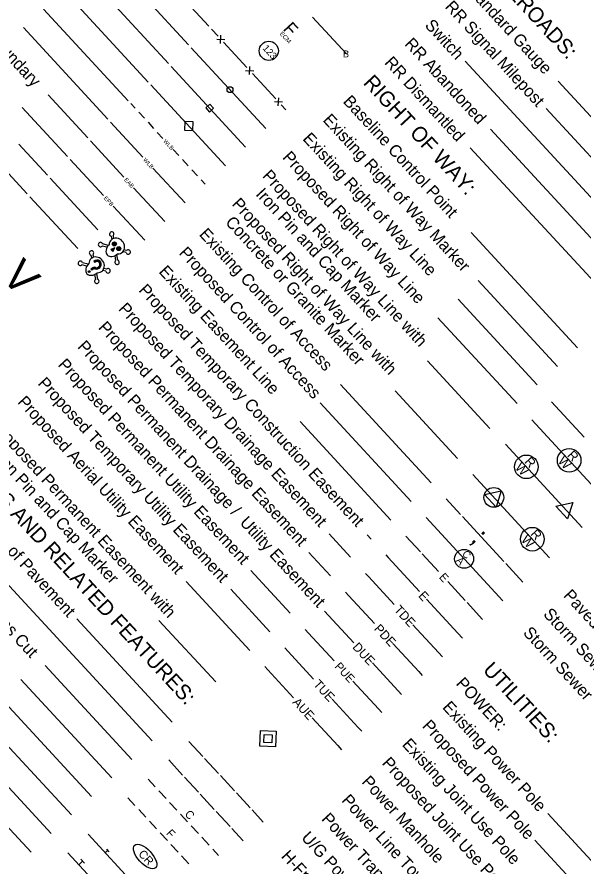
# Model space of a CAD drawing. Extents: x 1695041 to 1706254, y 786537 to 798223.
# Drawn here: x 1700036 to 1700861, y 791621 to 792859 of the extents above; entities that cross this region are included whole.
import ezdxf

# ---------------------------------------------------------------- set-up
doc = ezdxf.new("R2010")
doc.units = 0
for name, color, linetype in [('Prop Easement Permanent Drainage Utility', 7, 'Continuous'), ('Prop ROW Permanent Easement CELL', 7, 'Continuous'), ('Prop WCC CELL', 7, 'Continuous'), ('Sheet Symbology CELL', 7, 'Continuous')]:
    doc.layers.add(name, color=color, linetype=linetype)

msp = doc.modelspace()

# ---------------------------------------------------------------- linework, layer by layer
at = {"layer": 'Prop Easement Permanent Drainage Utility'}
for p, q in [((1700484.5, 791993.8), (1700527, 791947.8)), ((1700554.1, 791918.5), (1700596.4, 791872.6))]:
    msp.add_line(p, q, dxfattribs=at)
at = {"layer": 'Prop ROW Permanent Easement CELL'}
msp.add_line((1700401.9, 791808.3), (1700401.9, 791808.3), dxfattribs=at)
for points in [[(1700413.8, 791819.3), (1700412.8, 791796.5), (1700390.1, 791797.4), (1700391, 791820.2)], [(1700407.8, 791813.8), (1700407.4, 791802.4), (1700396, 791802.9), (1700396.5, 791814.3)]]:
    msp.add_lwpolyline(points, close=True, dxfattribs=at)
at = {"layer": 'Prop WCC CELL'}
msp.add_ellipse((1700222.8, 791636.7), major_axis=(15.2, -16.5), ratio=0.462467, dxfattribs=at)
at = {"layer": 'Sheet Symbology CELL'}
for p, q in [((1700315.6, 792846), (1700118.7, 793059.3)), ((1700286.2, 792818.9), (1700162.9, 792952.4)), ((1700256.8, 792791.7), (1700133.5, 792925.2)), ((1700227.4, 792764.6), (1700104.2, 792898.1)), ((1700198, 792737.5), (1700074.8, 792871)), ((1700467, 792858.9), (1700516.2, 792805.6)), ((1700168.6, 792710.4), (1700045.4, 792843.9)), ((1700168.6, 792710.4), (1700045.4, 792843.9)), ((1700319.5, 792841.8), (1700329.1, 792831.4)), ((1700332.9, 792821), (1700333.4, 792832.9)), ((1700327.2, 792827.2), (1700339.1, 792826.7)), ((1700337.2, 792822.5), (1700354.2, 792804.2)), ((1700290.1, 792814.7), (1700398.6, 792697.1)), ((1700290.1, 792814.7), (1700398.6, 792697.1)), ((1700354.2, 792804.2), (1700371.1, 792785.8)), ((1700260.7, 792787.5), (1700369.2, 792670)), ((1700260.7, 792787.5), (1700369.2, 792670)), ((1700375, 792775.5), (1700375.4, 792787.3)), ((1700980.9, 792479), (1700689.4, 792794.9)), ((1700369.3, 792781.6), (1700381.1, 792781.1)), ((1700379.3, 792777), (1700396.2, 792758.6)), ((1700231.3, 792760.4), (1700339.8, 792642.8)), ((1700231.3, 792760.4), (1700339.8, 792642.8)), ((1700396.2, 792758.6), (1700413.2, 792740.2)), ((1701039.7, 792533.3), (1700824.8, 792766.1)), ((1700139.2, 792683.2), (1700081.3, 792745.9)), ((1700201.9, 792733.3), (1700208.1, 792726.5)), ((1700411.3, 792736.1), (1700423.2, 792735.6)), ((1700417, 792729.9), (1700417.5, 792741.8)), ((1700109.8, 792656.1), (1700043.7, 792727.7)), ((1700421.3, 792731.4), (1700428, 792724.2)), ((1701010.3, 792506.1), (1700807.5, 792725.9)), ((1700213.5, 792720.7), (1700221.7, 792711.8)), ((1700172.5, 792706.1), (1700219.4, 792655.3)), ((1700227.1, 792706), (1700235.2, 792697.1)), ((1700951.5, 792451.9), (1700726.1, 792696.1)), ((1700240.6, 792691.3), (1700248.8, 792682.5)), ((1700080.4, 792629), (1700038.6, 792674.3)), ((1700143.1, 792679), (1700191.8, 792626.3)), ((1700263.7, 792666.3), (1700271.8, 792657.5)), ((1700922.2, 792424.7), (1700696.7, 792668.9)), ((1700922.2, 792424.7), (1700696.7, 792668.9)), ((1700113.7, 792651.9), (1700162.1, 792599.5)), ((1700277.3, 792651.6), (1700285.4, 792642.8)), ((1700051, 792601.8), (1700018.5, 792637.1)), ((1700234.3, 792639.2), (1700281, 792588.6)), ((1700290.8, 792636.9), (1700299, 792628.1)), ((1700084.3, 792624.8), (1700154.1, 792549.2)), ((1700304.4, 792622.2), (1700310.4, 792615.7)), ((1700206.1, 792610.7), (1700251.6, 792561.4)), ((1700054.9, 792597.6), (1700124.7, 792522)), ((1700176.5, 792583.9), (1700222.3, 792534.3)), ((1700173.2, 792540.1), (1700174.1, 792535.3)), ((1700176.2, 792540.6), (1700176.9, 792536.8)), ((1700853.1, 792377.7), (1700698.1, 792545.5)), ((1700167.2, 792523.9), (1700160.2, 792525.8)), ((1700169.1, 792526.6), (1700161, 792528.8)), ((1700143.8, 792512.7), (1700144.7, 792507.9)), ((1700146.8, 792513.2), (1700147.5, 792509.4)), ((1700178, 792522.6), (1700178, 792522.6)), ((1700178.5, 792511.7), (1700179.9, 792504.5)), ((1700181.3, 792513.3), (1700182.8, 792505.1)), ((1700195.1, 792516.4), (1700190.4, 792517.6)), ((1700195.9, 792519.3), (1700192.1, 792520.3)), ((1700137.8, 792496.5), (1700130.7, 792498.4)), ((1700139.6, 792499.2), (1700131.5, 792501.3)), ((1700148.2, 792503.3), (1700149.5, 792501.9)), ((1700145.1, 792493.2), (1700143.8, 792492.1)), ((1700143.8, 792492.1), (1700145.1, 792490.7)), ((1700145.3, 792493), (1700144, 792491.9)), ((1700145.4, 792492.8), (1700144.2, 792491.7)), ((1700145.6, 792492.6), (1700144.4, 792491.5)), ((1700145.8, 792492.4), (1700144.6, 792491.3)), ((1700146, 792492.2), (1700144.8, 792491.1)), ((1700146.2, 792492), (1700144.9, 792490.9)), ((1700146.4, 792491.8), (1700145.1, 792490.7)), ((1700149.3, 792495.8), (1700149.3, 792495.8)), ((1700151.8, 792485.9), (1700153.4, 792477.7)), ((1700165.6, 792489), (1700161, 792490.2)), ((1700166.4, 792491.9), (1700162.7, 792492.9)), ((1700149.1, 792484.3), (1700150.4, 792477.1)), ((1700823.7, 792350.5), (1700708.4, 792475.4)), ((1700794.3, 792323.4), (1700679, 792448.2)), ((1700764.9, 792296.3), (1700649.7, 792421.1)), ((1700725.4, 792259.9), (1700634.4, 792358.5)), ((1700640, 792181), (1700507.6, 792324.3)), ((1700678.3, 792216.4), (1700587.3, 792315)), ((1700610.6, 792153.8), (1700478.2, 792297.2)), ((1700815.2, 792299.1), (1700862.7, 792247.6)), ((1700581.2, 792126.7), (1700448.8, 792270.1)), ((1700786.4, 792272.6), (1700898.4, 792151.3)), ((1700748, 792237.1), (1700860, 792115.9)), ((1700700.3, 792193), (1700812.2, 792071.8)), ((1700661.7, 792157.4), (1700682.7, 792134.7)), ((1700731.1, 792159.7), (1700731.1, 792159.7)), ((1700835.5, 792142.4), (1700835.5, 792142.4)), ((1700632.3, 792130.3), (1700744.2, 792009)), ((1700685.4, 792131.8), (1700745.6, 792066.5)), ((1700522.4, 792072.5), (1700491, 792106.5)), ((1700552.3, 792099), (1700546.6, 792105.2)), ((1700602.9, 792103.2), (1700624, 792080.4)), ((1700493, 792045.3), (1700461.6, 792079.3)), ((1700626.7, 792077.4), (1700650.4, 792051.7)), ((1700573.5, 792076), (1700577.1, 792072.2)), ((1700577.1, 792072.2), (1700622.9, 792022.6)), ((1700434.2, 791991), (1700377, 792053)), ((1700748.4, 792063.5), (1700773.6, 792036.2)), ((1700232.9, 791805.2), (1700006.1, 792050.9)), ((1700544.1, 792048.9), (1700548.7, 792044)), ((1700548.7, 792044), (1700586, 792003.6)), ((1700375.4, 791936.8), (1700282.6, 792037.4)), ((1700664, 792037), (1700689.4, 792009.4)), ((1700404.8, 791963.9), (1700347.6, 792025.8)), ((1700514.7, 792021.8), (1700519.9, 792016.2)), ((1700519.9, 792016.2), (1700557.2, 791975.8)), ((1700633, 792011.6), (1700678.8, 791962)), ((1700692.1, 792006.5), (1700714.8, 791981.9)), ((1700262.3, 791832.4), (1700123.4, 791982.8)), ((1700325.7, 791890.9), (1700242.9, 791980.6)), ((1700455.9, 791967.5), (1700461.2, 791961.8)), ((1700613.1, 791974.2), (1700650.4, 791933.7)), ((1700461.2, 791961.8), (1700498.5, 791921.4)), ((1700678.8, 791962), (1700685.4, 791954.8)), ((1700584.3, 791946.4), (1700621.6, 791906)), ((1700426.6, 791940.4), (1700431.1, 791935.4)), ((1700431.1, 791935.4), (1700468.4, 791895)), ((1700650.4, 791933.7), (1700656.1, 791927.7)), ((1700203.5, 791778.1), (1700077.1, 791915)), ((1700397.2, 791913.2), (1700401.7, 791908.3)), ((1700401.7, 791908.3), (1700439, 791867.9)), ((1700621.6, 791906), (1700626.7, 791900.5)), ((1700144.7, 791723.8), (1699980.7, 791901.5)), ((1700174.1, 791751), (1700041.5, 791894.6)), ((1700525.6, 791892), (1700562.9, 791851.6)), ((1700085.9, 791670), (1699901.1, 791870.2)), ((1700115.3, 791697.1), (1699959.5, 791865.9)), ((1700495.5, 791865.6), (1700532.8, 791825.2)), ((1700562.9, 791851.6), (1700567.9, 791846.2)), ((1700466.1, 791838.5), (1700503.5, 791798.1)), ((1700532.8, 791825.2), (1700538.5, 791819.1)), ((1700056.5, 791642.8), (1699915, 791796.1)), ((1700286.6, 791804.3), (1700306.9, 791782.3)), ((1700503.5, 791798.1), (1700509.1, 791792)), ((1700257.2, 791777.2), (1700277.5, 791755.2)), ((1700309.6, 791779.4), (1700330, 791757.3)), ((1700227.1, 791749.4), (1700237.4, 791738.3)), ((1700280.2, 791752.2), (1700300.6, 791730.2)), ((1700332.7, 791754.4), (1700353.1, 791732.3)), ((1700253.3, 791721.1), (1700243, 791732.2)), ((1700197.7, 791722.3), (1700208, 791711.1)), ((1700303.3, 791727.2), (1700323.7, 791705.2)), ((1700355.8, 791729.4), (1700376.1, 791707.4)), ((1700268.9, 791704.2), (1700258.6, 791715.3)), ((1700223.9, 791693.9), (1700213.6, 791705)), ((1700284.8, 791686.9), (1700274.2, 791698.4)), ((1700326.4, 791702.3), (1700346.7, 791680.2)), ((1700378.8, 791704.4), (1700395.1, 791686.8)), ((1700997.9, 791495.3), (1700809.8, 791699.1)), ((1700239.5, 791677), (1700229.2, 791688.2)), ((1700300.4, 791670.1), (1700289.8, 791681.5)), ((1700139.6, 791669.1), (1700248.1, 791551.5)), ((1700255.4, 791659.8), (1700244.8, 791671.2)), ((1700349.4, 791677.3), (1700365.7, 791659.6)), ((1700316, 791653.1), (1700305.4, 791664.6)), ((1700968.5, 791468.1), (1700790.9, 791660.5)), ((1700164.5, 791642.1), (1700168.2, 791645.5)), ((1700166.5, 791647.3), (1700169.9, 791643.6)), ((1700271, 791642.9), (1700260.4, 791654.3)), ((1700330, 791638), (1700321.3, 791647.4)), ((1700218.7, 791524.4), (1700110.2, 791642)), ((1700129.2, 791633), (1700134.6, 791627.1)), ((1700286.6, 791626), (1700276, 791637.5)), ((1700126.1, 791624.7), (1700131.9, 791630.1))]:
    msp.add_line(p, q, dxfattribs=at)
for points in [[(1700311.1, 792726.9), (1700316.6, 792720.9), (1700322.7, 792726.4), (1700317.1, 792732.4)], [(1700280, 792694.6), (1700292.5, 792694.1), (1700293, 792706.6), (1700280.5, 792707)], [(1700178.8, 792523.2), (1700173, 792520.9), (1700175.9, 792517.7)], [(1700178, 792522.6), (1700173.6, 792520.7), (1700175.9, 792518.3)], [(1700177.3, 792521.9), (1700174.2, 792520.6), (1700175.8, 792518.9)], [(1700176.6, 792521.2), (1700174.8, 792520.5), (1700175.7, 792519.5)], [(1700175.9, 792520.6), (1700175.4, 792520.3), (1700175.6, 792520.1)], [(1700717.3, 792164), (1700741.7, 792169.4), (1700734.3, 792145.6)], [(1700821.7, 792146.7), (1700846.1, 792152.2), (1700838.7, 792128.3)]]:
    msp.add_lwpolyline(points, close=True, dxfattribs=at)
for centre, radius in [((1700403.1, 792810.1), 14), ((1700346.5, 792753.6), 4.3), ((1700178, 792528.9), 2.88), ((1700178, 792528.9), 2.54), ((1700178, 792528.9), 2.2), ((1700178, 792528.9), 1.86), ((1700178, 792528.9), 1.52), ((1700178, 792528.9), 1.18), ((1700178, 792528.9), 0.843), ((1700178, 792528.9), 0.503), ((1700178, 792528.9), 0.163), ((1700184.4, 792522), 2.88), ((1700184.4, 792522), 2.54), ((1700184.4, 792522), 2.2), ((1700184.4, 792522), 1.86), ((1700184.4, 792522), 1.52), ((1700184.4, 792522), 1.18), ((1700184.4, 792522), 0.843), ((1700184.4, 792522), 0.503), ((1700184.4, 792522), 0.163), ((1700141.4, 792488.5), 1.38), ((1700141.4, 792488.5), 1.07), ((1700141.4, 792488.5), 0.759), ((1700141.4, 792488.5), 0.453), ((1700141.4, 792488.5), 0.147), ((1700840.9, 792213.6), 17.2), ((1700778.5, 792204.2), 17.2), ((1700731.1, 792159.7), 14.4), ((1700787.2, 792098.8), 17.2), ((1700687.8, 792070.2), 13.8)]:
    msp.add_circle(centre, radius, dxfattribs=at)
for centre, start, end in [((1700174.2, 792543.1), 308.6067, 252.5152), ((1700157.8, 792528), 12.9029, 316.8115), ((1700144.7, 792515.7), 308.6067, 252.5152), ((1700198.2, 792517.1), 192.9029, 136.8115), ((1700128.4, 792500.6), 12.9029, 316.8115), ((1700181.9, 792502), 128.6067, 72.5152), ((1700168.8, 792489.7), 192.9029, 136.8115), ((1700152.4, 792474.6), 128.6067, 72.5152)]:
    msp.add_arc(centre, 3.22, start, end, dxfattribs=at)
for centre, major_axis, ratio, start_param, end_param in [((1700181.6, 792525.8), (8.2, -8.88), 0.885014, 5.564242, 10.143721), ((1700176.5, 792521.1), (-8.88, -8.2), 0.752542, 4.722735, 7.843636), ((1700152.1, 792498.4), (8.2, -8.88), 0.885014, 5.564242, 10.143721), ((1700147, 792493.7), (-8.88, -8.2), 0.752542, 4.722735, 7.843636), ((1700152.4, 792498.7), (5.1, 4.7), 0.9, 3.567618, 7.853982), ((1700152.4, 792498.7), (4.87, 4.5), 0.9, 3.567618, 7.853982), ((1700152.4, 792498.7), (4.65, 4.29), 0.9, 3.567618, 7.853982), ((1700152.4, 792498.7), (4.42, 4.08), 0.9, 3.567618, 7.853982), ((1700152.4, 792498.7), (4.2, 3.87), 0.9, 3.567618, 7.853982), ((1700152.4, 792498.7), (3.97, 3.67), 0.9, 3.567618, 7.853982), ((1700152.4, 792498.7), (3.75, 3.46), 0.9, 3.567618, 7.853982), ((1700152.4, 792498.7), (3.52, 3.25), 0.9, 3.567618, 7.853982), ((1700148.2, 792489.8), (3.82, 3.53), 0.9, 0.426026, 1.570796), ((1700148.2, 792489.8), (3.6, 3.32), 0.9, 0.426026, 1.570796), ((1700148.2, 792489.8), (3.37, 3.11), 0.9, 0.426026, 1.570796), ((1700148.2, 792489.8), (3.15, 2.91), 0.9, 0.426026, 1.570796), ((1700148.2, 792489.8), (2.92, 2.7), 0.9, 0.426026, 1.570796), ((1700148.2, 792489.8), (2.7, 2.49), 0.9, 0.426026, 1.570796), ((1700148.2, 792489.8), (2.47, 2.28), 0.9, 0.426026, 1.570796), ((1700148.2, 792489.8), (2.25, 2.08), 0.9, 0.426026, 1.570796)]:
    msp.add_ellipse(centre, major_axis=major_axis, ratio=ratio, start_param=start_param, end_param=end_param, dxfattribs=at)

# ---------------------------------------------------------------- texts
at = {"layer": 'Prop Easement Permanent Drainage Utility'}
msp.add_text('DUE', height=13.1, rotation=312.7091, dxfattribs=at).set_placement((1700524.3, 791941))
at = {"layer": 'Prop WCC CELL'}
msp.add_text('CR', height=12, rotation=312.7091, dxfattribs=at).set_placement((1700212.1, 791639.6))
at = {"layer": 'Sheet Symbology CELL'}
for s, height, rotation, p in [('Existing Endangered Animal Boundary', 17.5, 312.7091, (1699787.8, 793050.6)), ('CONVENTIONAL  PLAN SHEET SYMBOLS', 54.401, 312.7091, (1700806.2, 792986.3)), ('RAILROADS:', 22, 312.7091, (1700718, 792927.3)), ('Standard Gauge', 17.5, 312.7091, (1700688.3, 792900.7)), ('RR Signal Milepost', 17.5, 312.7091, (1700658.9, 792873.5)), ('F', 18.8, 312.7091, (1700423, 792841.3)), ('Switch', 17.5, 312.7091, (1700629.5, 792846.4)), ('ECM', 6.4, 312.7091, (1700418.5, 792834.7)), ('RR Abandoned', 17.5, 312.7091, (1700600.1, 792819.3)), ('123', 10, 312.7091, (1700393.4, 792813.3)), ('B', 10, 357.7092, (1700511, 792800.8)), ('RR Dismantled', 17.5, 312.7091, (1700570.7, 792792.1)), ('RIGHT OF WAY:', 22, 312.7091, (1700539.7, 792762.7)), ('Baseline Control Point', 17.5, 312.7091, (1700510.3, 792735.6)), ('Existing Right of Way Marker', 17.5, 312.7091, (1700480.9, 792708.5)), ('Existing Right of Way Line', 17.5, 312.7091, (1700451.5, 792681.3)), ('WLB', 6, 312.7091, (1700248.8, 792678.1)), ('Proposed Right of Way Line', 17.5, 312.7091, (1700422.1, 792654.2)), ('WLB', 6, 312.7091, (1700219.4, 792650.9)), ('Proposed Right of Way Line with', 17.5, 312.7091, (1700392.7, 792627.1)), ('EAB', 6, 312.7091, (1700191.7, 792621.9)), ('  Iron Pin and Cap Marker', 17.5, 312.7091, (1700374.3, 792610.1)), ('EPB', 6, 312.7091, (1700162, 792595.1)), ('Proposed Right of Way Line with', 17.5, 312.7091, (1700348.3, 792586.1)), ('  Concrete or Granite Marker', 17.5, 312.7091, (1700329.9, 792569.1)), ('Existing Control of Access', 17.5, 312.7091, (1700300.6, 792542)), ('Proposed Control of Access', 17.5, 312.7091, (1700271.2, 792514.9)), ('V', 45, 312.7091, (1700012.1, 792479.9)), ('Existing Easement Line', 17.5, 312.7091, (1700241.8, 792487.7)), ('Proposed Temporary Construction Easement', 17.5, 312.7091, (1700212.4, 792460.6)), ('Proposed Temporary Drainage Easement', 17.5, 312.7091, (1700183, 792433.5)), ('Proposed Permanent Drainage Easement', 17.5, 312.7091, (1700153.6, 792406.3)), ('Proposed Permanent Drainage /  Utility Easement', 17.5, 312.7091, (1700123.3, 792378.4)), ('Proposed Permanent Utility Easement', 17.5, 312.7091, (1700094.8, 792352.1)), ('Proposed Temporary Utility Easement', 17.5, 312.7091, (1700065.4, 792324.9)), ('Proposed Aerial Utility Easement', 17.5, 312.7091, (1700036, 792297.8)), ('Proposed Permanent Easement with', 17.5, 312.7091, (1699998, 792262.7)), ('ROADS AND RELATED FEATURES:', 22, 312.7091, (1699948.9, 792217.4)), ('Iron Pin and Cap Marker', 17.5, 312.7091, (1700000.5, 792219.4)), ('R', 13.5, 312.7091, (1700837.3, 792220.4)), ('R', 13.5, 312.7091, (1700774.9, 792211)), ('W', 13.5, 312.7091, (1700823.6, 792211.9)), ('Existing Edge of Pavement', 17.5, 312.7091, (1699919.5, 792190.3)), ('W', 13.5, 312.7091, (1700761.2, 792202.5)), ('Proposed Slope Stakes Cut', 17.5, 312.7091, (1699860.7, 792136)), (';', 30, 312.7091, (1700696.5, 792097.6)), ('W', 13.5, 312.7091, (1700769.9, 792097.1)), ('R', 13.5, 312.7091, (1700783.7, 792105.7)), ('C', 10.8, 312.7091, (1700684, 792076.7)), ('A', 10.8, 312.7091, (1700675.2, 792067.1)), ('E', 12, 312.7091, (1700650.4, 792042.9)), ('E', 13.1, 312.7091, (1700620.2, 792015.8)), ('Paved Ditch Gutter', 17.5, 312.7091, (1700831.5, 792015.9)), ('TDE', 13.1, 312.7091, (1700584.7, 791995.3)), ('Storm Sewer Manhole', 17.5, 312.7091, (1700802.1, 791988.8)), ('PDE', 13.1, 312.7091, (1700555.7, 791967.6)), ('Storm Sewer', 17.5, 312.7091, (1700772.7, 791961.7)), ('PUE', 12, 312.7091, (1700498.3, 791912.8)), ('UTILITIES:', 22, 312.7091, (1700713.9, 791907.4)), ('TUE', 13.1, 312.7091, (1700467.1, 791886.8)), ('POWER:', 17.5, 312.7091, (1700674.9, 791887.8)), ('AUE', 13.1, 312.7091, (1700436.8, 791860.6)), ('Existing Power Pole', 17.5, 312.7091, (1700655.2, 791853.2)), ('Proposed Power Pole', 17.5, 312.7091, (1700625.8, 791826)), ('Existing Joint Use Pole', 17.5, 312.7091, (1700596.4, 791798.9)), ('Proposed Joint Use Pole', 17.5, 312.7091, (1700567, 791771.8)), ('Power Manhole', 17.5, 312.7091, (1700537.6, 791744.6)), ('Power Line Tower', 17.5, 312.7091, (1700508.2, 791717.5)), ('C', 11.9, 312.7091, (1700279.6, 791697.7)), ('Power Transformer', 17.5, 312.7091, (1700478.8, 791690.4)), ('F', 11.9, 312.7091, (1700252.7, 791669.7)), ('U/G Power Cable Hand Hole', 17.5, 312.7091, (1700449.5, 791663.2)), ('H-Frame Pole', 17.5, 312.7091, (1700420.1, 791636.1))]:
    msp.add_text(s, height=height, rotation=rotation, dxfattribs=at).set_placement(p)

doc.saveas('drawing.dxf')
